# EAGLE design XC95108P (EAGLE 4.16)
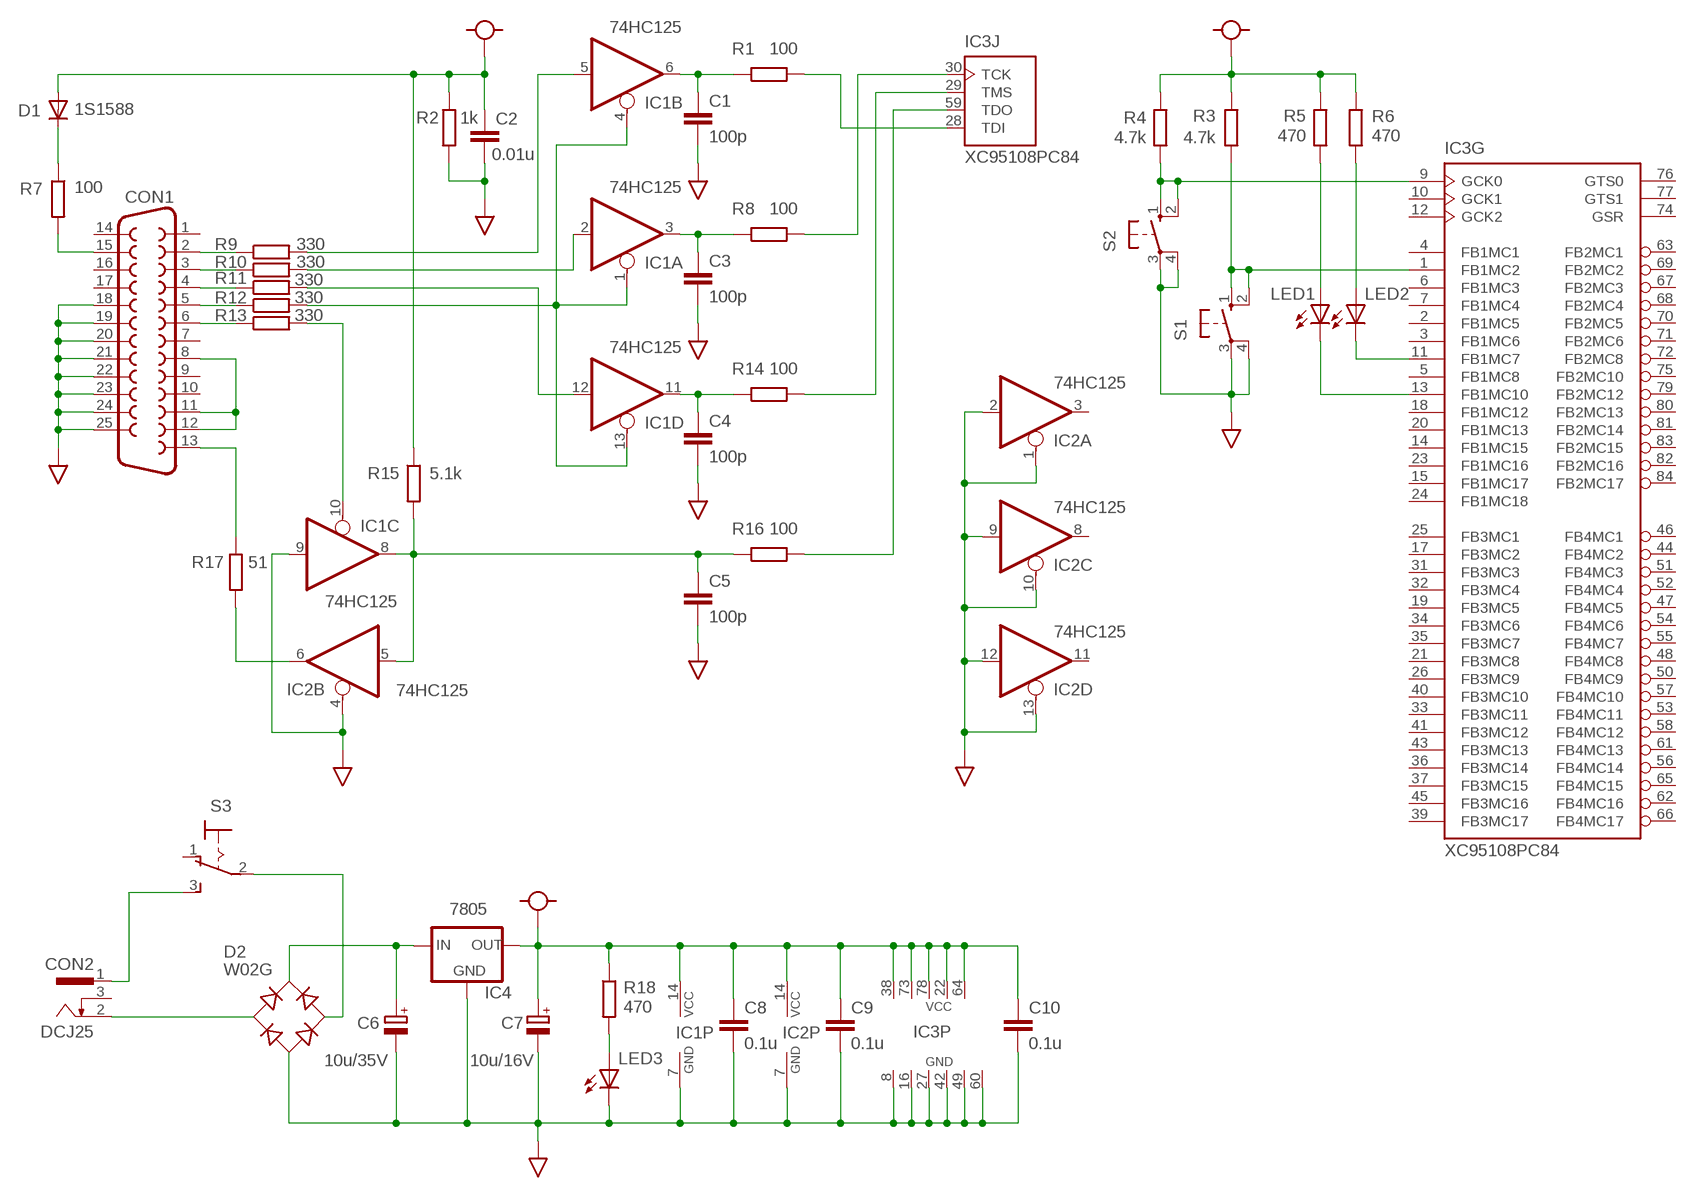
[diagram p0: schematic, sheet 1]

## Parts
C1  100p  C-CERAMIC  [C025-025X050]
C2  0.01u  C-PASS  [PASSCON]
C3  100p  C-CERAMIC  [C025-025X050]
C4  100p  C-CERAMIC  [C025-025X050]
C5  100p  C-CERAMIC  [C025-025X050]
C6  10u/35V  C-TANTALUM  [C4518]
C7  10u/16V  C-TANTALUM  [C4518]
C8  0.1u  C-PASS  [PASSCON]
C9  0.1u  C-PASS  [PASSCON]
C10  0.1u  C-PASS  [PASSCON]
CON1  DSUB25P  [F25H]
CON2  DCJ25  [SCD-014-A]
D1  1S1588  [DO41-10]
D2  W02G  [RB1A]
IC1  74HC125  74125  [DIL14]
IC2  74HC125  74125  [DIL14]
IC3  XC95108PC84  XC9572PC84  [PLCC-S84]
IC4  7805  78XXL  [78XXL]
LED1  LED3MM  [LED3MM]
LED2  LED3MM  [LED3MM]
LED3  LED3MM  [LED3MM]
R1  100  R1/8W  [0207/10]
R2  1k  R1/8W  [0207/10]
R3  4.7k  R1/8W  [0207/10]
R4  4.7k  R1/8W  [0207/10]
R5  470  R1/8W  [0207/10]
R6  470  R1/8W  [0207/10]
R7  100  R1/8W  [0207/10]
R8  100  R1/8W  [0207/10]
R9  330  R1/8W  [0207/10]
R10  330  R1/8W  [0207/10]
R11  330  R1/8W  [0207/10]
R12  330  R1/8W  [0207/10]
R13  330  R1/8W  [0207/10]
R14  100  R1/8W  [0207/10]
R15  5.1k  R1/8W  [0207/10]
R16  100  R1/8W  [0207/10]
R17  51  R1/8W  [0207/10]
R18  470  R1/8W  [0207/10]
S1  40-XX  [B3F-40XX]
S2  40-XX  [B3F-40XX]
S3  SW-TOGGLE  [SW-TOGGLE]

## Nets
GND: C1.2 C2.2 C3.2 C4.2 C5.2 C6.- C7.- C8.2 C9.2 C10.2 CON1.18 CON1.19 CON1.20 CON1.21 CON1.22 CON1.23 CON1.24 CON1.25 D2.- IC1.7(P:GND) IC1.9(C:I) IC2.1(A:OE) IC2.2(A:I) IC2.4(B:OE) IC2.7(P:GND) IC2.9(C:I) IC2.10(C:OE) IC2.12(D:I) IC2.13(D:OE) IC3.8(P:GND) IC3.16(P:GND) IC3.27(P:GND) IC3.42(P:GND) IC3.49(P:GND) IC3.60(P:GND) IC4.GND LED3.K(C) R2.2 S1.3(P) S1.4(P1) S2.3(P) S2.4(P1)
N$1: CON1.4 R11.1
N$2: IC1.5(B:I) R9.2
N$3: CON1.2 R9.1
N$4: CON1.3 R10.1
N$5: IC1.2(A:I) R10.2
N$6: CON1.15 R7.2
N$7: CON1.8 CON1.11 CON1.12
N$8: CON1.5 R12.1
N$9: CON1.6 R13.1
N$10: IC1.12(D:I) R11.2
N$11: IC1.10(C:OE) R13.2
N$12: IC3.11(G:FB1MC7) LED2.K(C)
N$13: C3.1 IC1.3(A:O) R8.1
N$14: CON1.13 R17.1
N$15: D1.C R7.1
N$16: C5.1 IC1.8(C:O) IC2.5(B:I) R15.2 R16.1
N$17: LED3.A R18.2
N$18: C1.1 IC1.6(B:O) R1.1
N$19: IC2.6(B:O) R17.2
N$20: C4.1 IC1.11(D:O) R14.1
N$21 [AC]: CON2.2 D2.AC1
N$22: IC3.13(G:FB1MC10) LED1.K(C)
N$23 [AC]: C6.+ D2.+ IC4.IN
N$26: IC1.1(A:OE) IC1.4(B:OE) IC1.13(D:OE) R12.2
N$27: IC3.30(J:TCK) R8.2
N$28: IC3.29(J:TMS) R14.2
N$29: IC3.59(J:TDO) R16.2
N$30: IC3.28(J:TDI) R1.2
N$31: IC3.9(G:GCK0) R4.2 S2.1(S) S2.2(S1)
N$32: LED1.A R5.2
N$33: LED2.A R6.2
N$34 [AC]: D2.AC2 S3.2(P)
N$35: IC3.1(G:FB1MC2) R3.2 S1.1(S) S1.2(S1)
N$37 [AC]: CON2.1 S3.3(S)
VCC [Vcc]: C2.1 C7.+ C8.1 C9.1 C10.1 D1.A IC1.14(P:VCC) IC2.14(P:VCC) IC3.22(P:VCC) IC3.38(P:VCC) IC3.64(P:VCC) IC3.73(P:VCC) IC3.78(P:VCC) IC4.OUT R2.1 R3.1 R4.1 R5.1 R6.1 R15.1 R18.1
Unconnected: CON1.1 CON1.7 CON1.9 CON1.10 CON1.14 CON1.16 CON1.17 CON2.3 IC2.3(A:O) IC2.8(C:O) IC2.11(D:O) IC3.2(G:FB1MC5) IC3.3(G:FB1MC6) IC3.4(G:FB1MC1) IC3.5(G:FB1MC8) IC3.6(G:FB1MC3) IC3.7(G:FB1MC4) IC3.10(G:GCK1) IC3.12(G:GCK2) IC3.14(G:FB1MC15) IC3.15(G:FB1MC17) IC3.17(G:FB3MC2) IC3.18(G:FB1MC12) IC3.19(G:FB3MC5) IC3.20(G:FB1MC13) IC3.21(G:FB3MC8) IC3.23(G:FB1MC16) IC3.24(G:FB1MC18) IC3.25(G:FB3MC1) IC3.26(G:FB3MC9) IC3.31(G:FB3MC3) IC3.32(G:FB3MC4) IC3.33(G:FB3MC11) IC3.34(G:FB3MC6) IC3.35(G:FB3MC7) IC3.36(G:FB3MC14) IC3.37(G:FB3MC15) IC3.39(G:FB3MC17) IC3.40(G:FB3MC10) IC3.41(G:FB3MC12) IC3.43(G:FB3MC13) IC3.44(G:FB4MC2) IC3.45(G:FB3MC16) IC3.46(G:FB4MC1) IC3.47(G:FB4MC5) IC3.48(G:FB4MC8) IC3.50(G:FB4MC9) IC3.51(G:FB4MC3) IC3.52(G:FB4MC4) IC3.53(G:FB4MC11) IC3.54(G:FB4MC6) IC3.55(G:FB4MC7) IC3.56(G:FB4MC14) IC3.57(G:FB4MC10) IC3.58(G:FB4MC12) IC3.61(G:FB4MC13) IC3.62(G:FB4MC16) IC3.63(G:FB2MC1) IC3.65(G:FB4MC15) IC3.66(G:FB4MC17) IC3.67(G:FB2MC3) IC3.68(G:FB2MC4) IC3.69(G:FB2MC2) IC3.70(G:FB2MC5) IC3.71(G:FB2MC6) IC3.72(G:FB2MC8) IC3.74(G:GSR) IC3.75(G:FB2MC10) IC3.76(G:GTS0) IC3.77(G:GTS1) IC3.79(G:FB2MC12) IC3.80(G:FB2MC13) IC3.81(G:FB2MC14) IC3.82(G:FB2MC16) IC3.83(G:FB2MC15) IC3.84(G:FB2MC17) S3.1(O)

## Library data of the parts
C1 C3-C5 = xc95108p:C-CERAMIC: Ceramic Conenser
C2 C8-C10 = xc95108p:C-PASS: Monolithic Ceramic Condenser
C6 C7 = xc95108p:C-TANTALUM: Tantalum Condenser
CON1 = xc95108p:DSUB25P: IBM PC/AT Parallel Connector
CON2 = xc95108p:DCJ25: Standerd AC Adupter Jack
D1 = xc95108p:1S1588: Small Signal Diode
D2 = xc95108p:W02G: Bridge Diode
IC1 IC2 = xc95108p:74125: Quad bus BUFFER, 3-state
IC3 = XILINX:XC9572PC84: CPLD
IC4 = xc95108p:78XXL: Voltage Regurator, Up to 1A
LED1-LED3 = xc95108p:LED3MM: LED
R1-R18 = xc95108p:R1/8W: Carbon Resistor
S1 S2 = olimex-r0land:40-XX: OMRON SWITCH
S3 = xc95108p:SW-TOGGLE: Toggle Switch

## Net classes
1 AC: width 0.762 mm
2 Vcc: width 0.508 mm

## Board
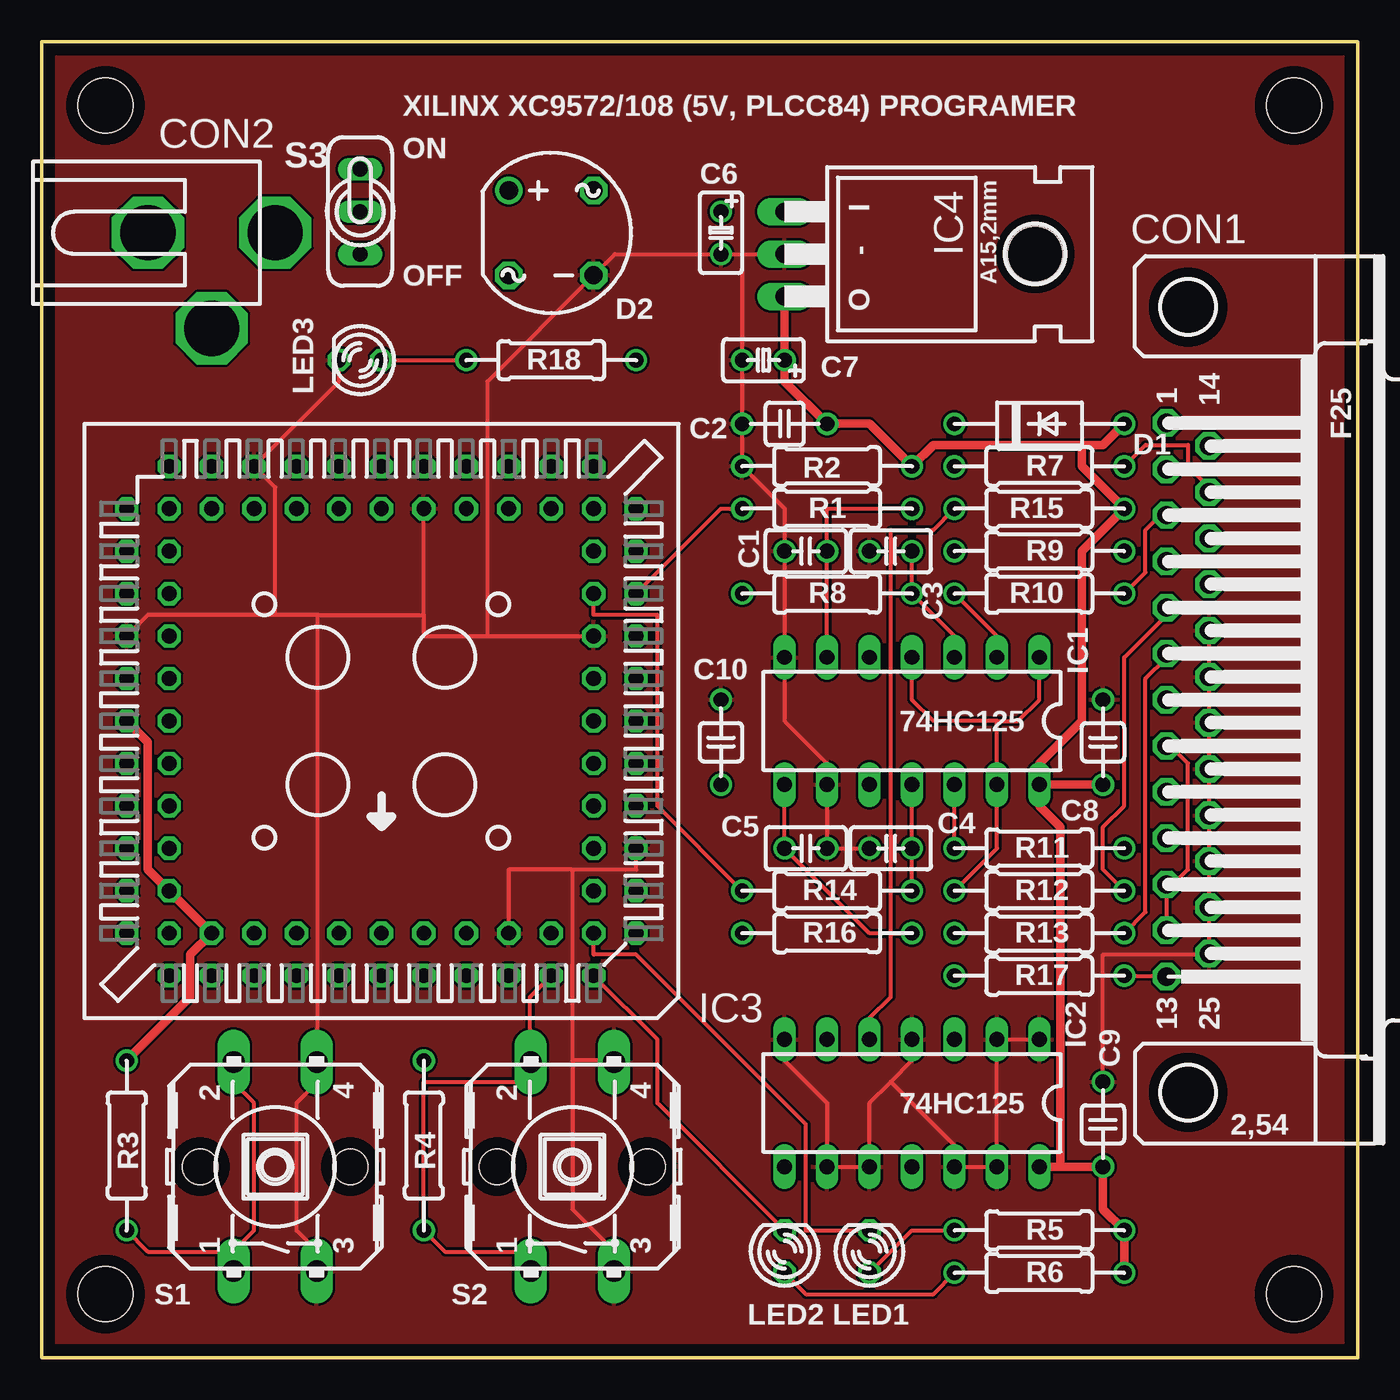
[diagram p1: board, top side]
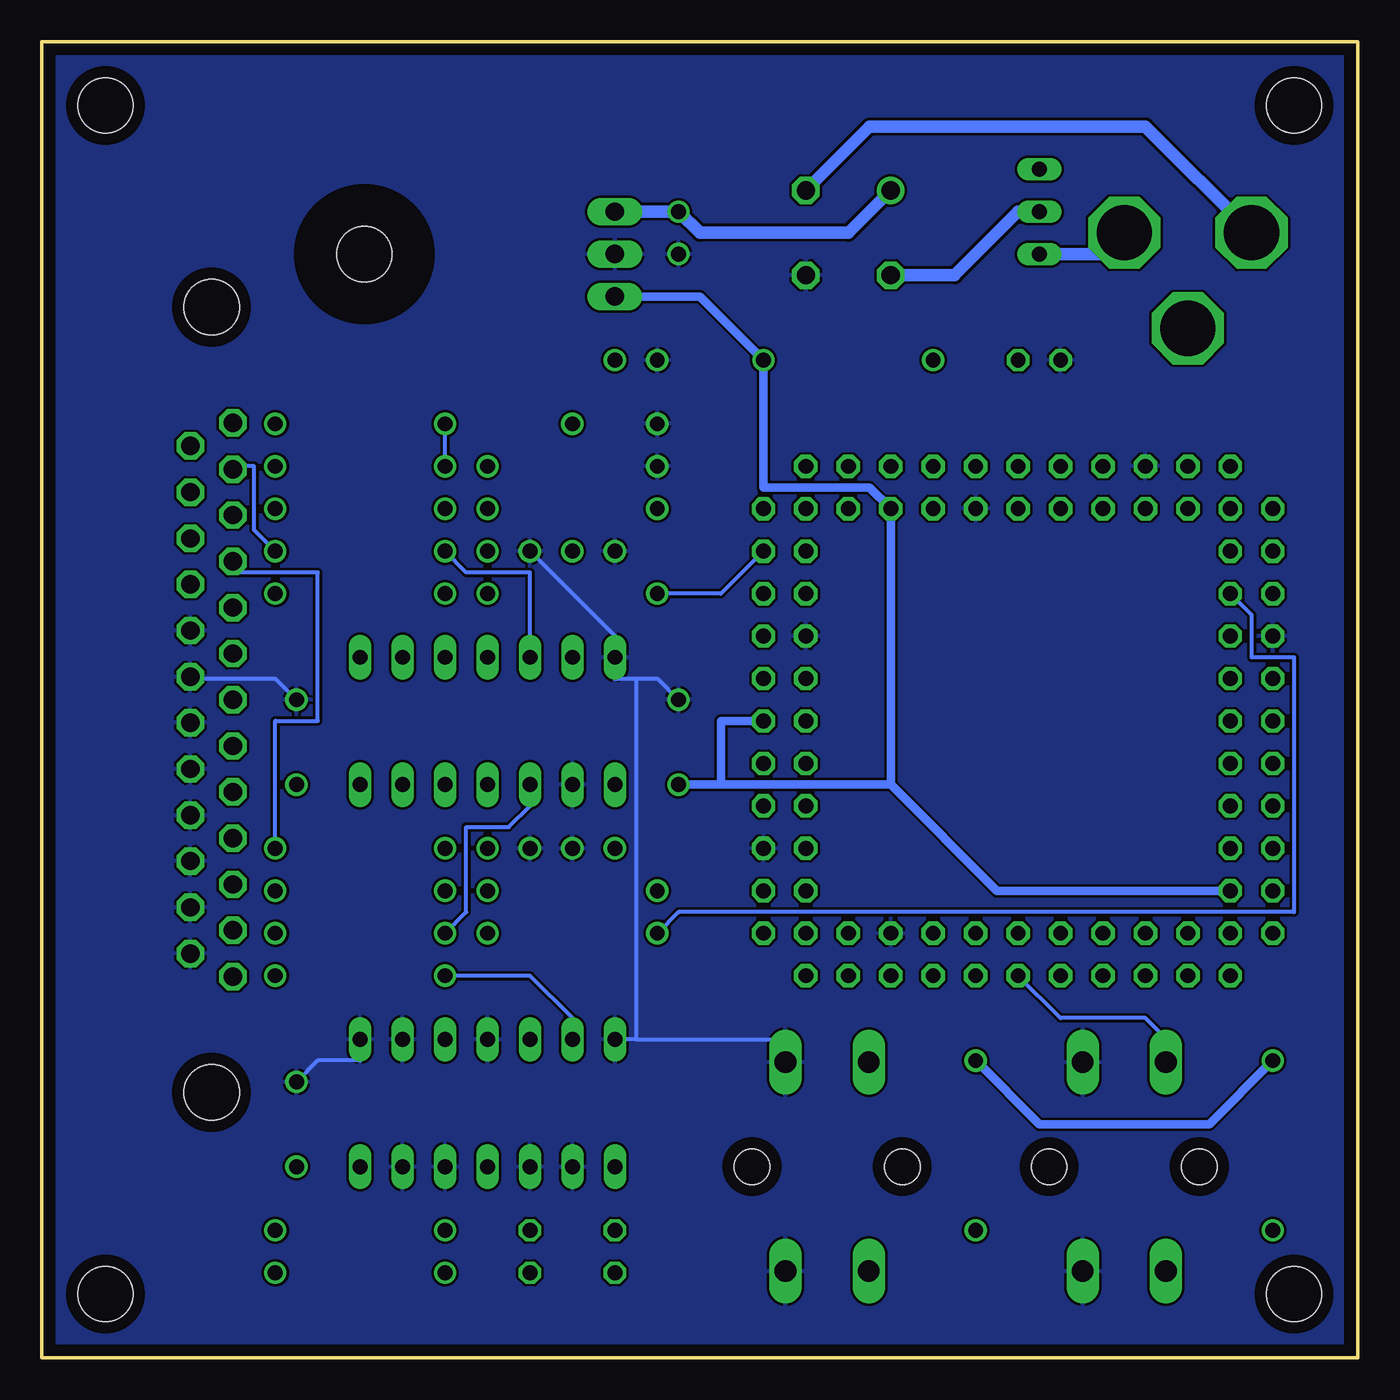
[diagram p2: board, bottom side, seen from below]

Size 78.74 x 78.74 mm. Coordinates in mm from the lower left corner, seen from the top.
Outline: 0,0 0,78.74 78.74,78.74 78.74,0 0,0
Copper layers (1*16): Top 0.035mm / dielectric 1.5mm / Bottom 0.035mm
Design rules "p-ban_min": minimum track width 0.15mm, minimum drill 0.3mm, track to track 0.15mm, track to pad 0.15mm, pad to pad 0.15mm, via to via 0.15mm, smd to smd 0.15mm, copper to edge 0.7mm, drill to drill 0.45mm, minimum pad ring 0.15mm, minimum via ring 0.15mm, stop-mask expansion 4mil, vias tented up to drill 0mil, thermal gap 0.15mm
Holes 3.3 mm at 74.93,74.93 74.93,3.81 3.81,3.81 3.81,74.93

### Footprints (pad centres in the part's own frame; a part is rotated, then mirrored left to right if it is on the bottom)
C025-025X050 = drill 0.889 round: 1 -1.27,0; 2 1.27,0
PASSCON = drill 0.889 round: 1 -1.27,0; 2 3.81,0
C4518 = drill 0.889 round: + -1.27,0; - 1.27,0
F25H = drill 1.092 octagon: 1 -16.561,-10.16; 2 -13.792,-10.16; 3 -11.049,-10.16; 4 -8.28,-10.16; 5 -5.512,-10.16; 6 -2.769,-10.16; 7 0,-10.16; 8 2.769,-10.16; 9 5.512,-10.16; 10 8.28,-10.16; 11 11.049,-10.16; 12 13.792,-10.16; 13 16.561,-10.16; 14 -15.189,-7.62; 15 -12.421,-7.62; 16 -9.652,-7.62; 17 -6.909,-7.62; 18 -4.14,-7.62; 19 -1.372,-7.62; 20 1.372,-7.62; 21 4.14,-7.62; 22 6.909,-7.62; 23 9.652,-7.62; 24 12.421,-7.62; 25 15.189,-7.62 | hole 3.302: -23.495,-8.89; 23.495,-8.89
SCD-014-A = drill 3.302 octagon: 1 0,12.065; 2 0,4.445; 3 5.715,8.255
DO41-10 = drill 0.889 round: A 5.08,0; C -5.08,0
RB1A = drill 1.092 round: + -2.54,2.54 | drill 1.092 octagon: - 2.54,-2.54; AC1 2.54,2.54; AC2 -2.54,-2.54
DIL14 = drill 0.889 long: 1 -7.62,-3.81; 2 -5.08,-3.81; 3 -2.54,-3.81; 4 0,-3.81; 5 2.54,-3.81; 6 5.08,-3.81; 7 7.62,-3.81; 8 7.62,3.81; 9 5.08,3.81; 10 2.54,3.81; 11 0,3.81; 12 -2.54,3.81; 13 -5.08,3.81; 14 -7.62,3.81
PLCC-S84 = drill 0.889 pad 1.397 octagon: 1 0,15.24; 2 0,12.7; 3 -2.54,15.24; 4 -2.54,12.7; 5 -5.08,15.24; 6 -5.08,12.7; 7 -7.62,15.24; 8 -7.62,12.7; 9 -10.16,15.24; 10 -10.16,12.7; 11 -12.7,15.24; 12 -15.24,12.7; 13 -12.7,12.7; 14 -15.24,10.16; 15 -12.7,10.16; 16 -15.24,7.62; 17 -12.7,7.62; 18 -15.24,5.08; 19 -12.7,5.08; 20 -15.24,2.54; 21 -12.7,2.54; 22 -15.24,0; 23 -12.7,0; 24 -15.24,-2.54; 25 -12.7,-2.54; 26 -15.24,-5.08; 27 -12.7,-5.08; 28 -15.24,-7.62; 29 -12.7,-7.62; 30 -15.24,-10.16; 31 -12.7,-10.16; 32 -15.24,-12.7; 33 -12.7,-15.24; 34 -12.7,-12.7; 35 -10.16,-15.24; 36 -10.16,-12.7; 37 -7.62,-15.24; 38 -7.62,-12.7; 39 -5.08,-15.24; 40 -5.08,-12.7; 41 -2.54,-15.24; 42 -2.54,-12.7; 43 0,-15.24; 44 0,-12.7; 45 2.54,-15.24; 46 2.54,-12.7; 47 5.08,-15.24; 48 5.08,-12.7; 49 7.62,-15.24; 50 7.62,-12.7; 51 10.16,-15.24; 52 10.16,-12.7; 53 12.7,-15.24; 54 15.24,-12.7; 55 12.7,-12.7; 56 15.24,-10.16; 57 12.7,-10.16; 58 15.24,-7.62; 59 12.7,-7.62; 60 15.24,-5.08; 61 12.7,-5.08; 62 15.24,-2.54; 63 12.7,-2.54; 64 15.24,0; 65 12.7,0; 66 15.24,2.54; 67 12.7,2.54; 68 15.24,5.08; 69 12.7,5.08; 70 15.24,7.62; 71 12.7,7.62; 72 15.24,10.16; 73 12.7,10.16; 74 15.24,12.7; 75 12.7,15.24; 76 12.7,12.7; 77 10.16,15.24; 78 10.16,12.7; 79 7.62,15.24; 80 7.62,12.7; 81 5.08,15.24; 82 5.08,12.7; 83 2.54,15.24; 84 2.54,12.7
78XXL = drill 1.092 long: GND 0,-3.81; IN -2.54,-3.81; OUT 2.54,-3.81 | hole 3.302: 0,11.176
LED3MM = drill 0.889 octagon: A -1.27,0; K 1.27,0
0207/10 = drill 0.889 round: 1 -5.08,0; 2 5.08,0
B3F-40XX = drill 1.295 long: 1 -6.248,2.489; 2 6.248,2.489; 3 -6.248,-2.489; 4 6.248,-2.489 | hole 2.108: 0,-4.496; 0,4.496
SW-TOGGLE = drill 0.889 long: 1 0,-2.54; 2 0,0; 3 0,2.54

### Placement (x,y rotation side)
C1  45.72,48.26 180 top
C2  45.72,55.88 180 top
C3  50.8,48.26 180 top
C4  50.8,30.48 180 top
C5  45.72,30.48 0 top
C6  40.64,67.31 270 top
C7  43.18,59.69 180 top
C8  63.5,35.56 90 top
C9  63.5,12.7 90 top
C10  40.64,35.56 90 top
CON1  77.47,39.37 270 top
CON2  1.91,67.31 270 top
D1  59.69,55.88 0 top
D2  30.48,67.31 0 top
IC1  52.07,38.1 180 top
IC2  52.07,15.24 180 top
IC3  20.32,38.1 180 top
IC4  48.26,66.04 270 top
LED1  49.53,6.35 90 top
LED2  44.45,6.35 90 top
LED3  19.05,59.69 180 top
R1  46.99,50.8 180 top
R2  46.99,53.34 180 top
R3  5.08,12.7 270 top
R4  22.86,12.7 270 top
R5  59.69,7.62 180 top
R6  59.69,5.08 180 top
R7  59.69,53.34 0 top
R8  46.99,45.72 180 top
R9  59.69,48.26 180 top
R10  59.69,45.72 180 top
R11  59.69,30.48 180 top
R12  59.69,27.94 180 top
R13  59.69,25.4 180 top
R14  46.99,27.94 180 top
R15  59.69,50.8 180 top
R16  46.99,25.4 180 top
R17  59.69,22.86 180 top
R18  30.48,59.69 180 top
S1  13.97,11.43 90 top
S2  31.75,11.43 90 top
S3  19.05,68.58 180 top

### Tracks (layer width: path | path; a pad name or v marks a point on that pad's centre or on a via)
GND
  Top 0.254: CON1.18 CON1.19 CON1.20 CON1.21 CON1.22 CON1.23 CON1.24 CON1.25 69.85,24.13 63.5,24.13 C9.2 | IC2.7 44.45,17.78 46.99,15.24 IC2.9 IC2.10 49.53,15.24 50.8,16.51 | 50.8,16.51 52.07,17.78 IC2.4 | IC2.1 IC2.2 IC2.13 IC2.12 54.61,12.7 50.8,16.51 | 31.75,29.21 27.94,29.21 IC3.8 | 31.75,29.21 35.56,29.21 IC3.16 | 31.75,17.78 31.75,29.21 | 31.75,17.78 31.75,8.89 34.29,6.35 S2.3 | 31.75,17.78 34.29,17.78 S2.4 | 41.91,66.04 C6.- 34.29,66.04 D2.- 26.67,58.42 26.67,43.18 | 41.91,66.04 IC4.GND | C4.2 C5.2 IC1.9 46.99,35.56 44.45,38.1 IC1.7 C1.2 44.45,50.8 R2.2 C2.2 C7.- 41.91,66.04 | S1.3 16.51,6.35 15.24,7.62 15.24,15.24 16.51,16.51 S1.4 16.51,19.05 16.51,44.45 | LED3.K 17.78,58.42 IC3.49 13.97,52.07 13.97,44.45 | IC3.60 6.35,44.45 13.97,44.45 | 16.51,44.45 22.86,44.45 | 16.51,44.45 13.97,44.45 | 22.86,44.45 IC3.42 | 26.67,43.18 22.86,43.18 22.86,44.45 | 26.67,43.18 IC3.27
  Bottom 0.254: C8.2 64.77,40.64 69.85,40.64 CON1.19 | C9.2 62.23,17.78 59.69,17.78 IC2.1 | 43.18,19.05 34.29,19.05 S2.4 | 43.18,19.05 IC2.7 | C10.2 41.91,40.64 43.18,40.64 | 43.18,40.64 44.45,40.64 IC1.7 44.45,43.18 C3.2 | 43.18,40.64 43.18,19.05
  pour Bottom: 0,78.74 78.74,78.74 78.74,0 0,0
  pour Top: 0,78.74 78.74,78.74 78.74,0 0,0
N$1
  Bottom 0.254: R11.1 64.77,38.1 62.23,38.1 62.23,46.99 67.31,46.99 CON1.4
N$2
  Bottom 0.254: R9.2 53.34,46.99 49.53,46.99 IC1.5
N$3
  Bottom 0.254: R9.1 66.04,49.53 66.04,53.34 67.31,53.34 CON1.2
N$4
  Top 0.254: R10.1 66.04,46.99 66.04,49.53 67.31,50.8 CON1.3
N$5
  Top 0.254: R10.2 57.15,43.18 IC1.2
N$6
  Top 0.254: R7.2 66.04,54.61 68.58,54.61 68.58,53.34 69.85,52.07 CON1.15
N$7
  Top 0.254: 67.31,27.94 CON1.12 67.31,25.4 | 67.31,27.94 68.58,29.21 68.58,35.56 67.31,36.83 CON1.8 | 67.31,27.94 CON1.11
N$8
  Top 0.254: R12.1 63.5,29.21 63.5,31.75 64.77,33.02 64.77,41.91 67.31,44.45 CON1.5
N$9
  Top 0.254: R13.1 66.04,26.67 66.04,40.64 67.31,41.91 CON1.6
N$10
  Top 0.254: R11.2 IC1.12
N$11
  Bottom 0.254: R13.2 53.34,26.67 53.34,31.75 50.8,31.75 49.53,33.02 IC1.10
N$12
  Top 0.254: LED2.K 36.83,15.24 36.83,19.05 IC3.11
N$13
  Top 0.254: C3.1 R8.1 54.61,43.18 IC1.3
N$14
  Top 0.254: R17.1 67.31,22.86 CON1.13
N$15
  Bottom 0.254: R7.1 D1.C
N$16
  Top 0.254: IC1.8 C5.1 49.53,25.4 50.8,25.4 | 50.8,25.4 R16.1 | IC2.5 49.53,20.32 50.8,21.59 50.8,25.4 | R15.2 53.34,49.53 50.8,49.53 50.8,25.4
N$17
  Top 0.254: LED3.A R18.2
N$18
  Top 0.254: IC1.6 C1.1 46.99,50.8 R1.1
N$19
  Bottom 0.254: R17.2 49.53,22.86 46.99,20.32 IC2.6
N$20
  Top 0.254: R14.1 C4.1 IC1.11
N$21
  Bottom 0.762: D2.AC1 29.21,73.66 12.7,73.66 CON2.2
N$22
  Top 0.254: LED1.K 45.72,7.62 45.72,13.97 35.56,24.13 33.02,24.13 IC3.13
N$23
  Bottom 0.762: IC4.IN C6.+ 39.37,67.31 30.48,67.31 D2.+
N$26
  Top 0.254: R12.2 57.15,30.48 IC1.13 57.15,38.1 | 57.15,38.1 53.34,38.1 52.07,39.37 IC1.4 | 57.15,38.1 58.42,38.1 59.69,39.37 IC1.1
N$27
  Bottom 0.254: IC3.30 38.1,45.72 R8.2
N$28
  Top 0.254: R14.2 36.83,33.02 36.83,44.45 33.02,44.45 IC3.29
N$29
  Bottom 0.254: IC3.59 6.35,44.45 6.35,41.91 3.81,41.91 3.81,26.67 40.64,26.67 R16.2
N$30
  Top 0.254: IC3.28 40.64,50.8 R1.2
N$31
  Top 0.254: IC3.9 29.21,21.59 29.21,19.05 S2.2 29.21,16.51 22.86,16.51 R4.2 24.13,6.35 29.21,6.35 S2.1
N$32
  Top 0.254: LED1.A 52.07,7.62 R5.2
N$33
  Top 0.254: LED2.A 45.72,3.81 53.34,3.81 R6.2
N$34
  Bottom 0.762: D2.AC2 24.13,64.77 20.32,68.58 S3.2
N$35
  Top 0.254: R3.2 6.35,6.35 11.43,6.35 | 11.43,6.35 12.7,7.62 12.7,15.24 11.43,16.51 S1.2 | 11.43,6.35 S1.1
  Bottom 0.254: S1.1 11.43,6.35 | IC3.1 17.78,20.32 12.7,20.32 11.43,19.05 S1.2
N$37
  Bottom 0.762: S3.3 15.24,66.04 CON2.1
VCC
  Top 0.508: R3.1 8.89,21.59 8.89,24.13 IC3.78 | IC3.78 IC3.73 | IC3.64 6.35,36.83 6.35,29.21 IC3.73 | IC3.78 IC3.73 | IC1.14 C8.1 | R6.1 R5.1 63.5,8.89 C9.1 60.96,11.43 | 60.96,11.43 IC2.14 | 60.96,11.43 60.96,31.75 59.69,33.02 IC1.14 | IC4.OUT C7.+ 44.45,58.42 C2.1 49.53,55.88 R2.1 53.34,54.61 62.23,54.61 | 62.23,54.61 62.23,53.34 R15.1 62.23,48.26 62.23,38.1 59.69,35.56 IC1.14 | 62.23,54.61 63.5,54.61 D1.A
  Bottom 0.508: 27.94,34.29 IC3.38 29.21,52.07 35.56,52.07 R18.1 39.37,63.5 IC4.OUT | 39.37,34.29 C10.1 | 27.94,34.29 39.37,34.29 | 39.37,34.29 38.1,34.29 38.1,38.1 IC3.22 | R4.1 19.05,13.97 8.89,13.97 R3.1 | 27.94,34.29 21.59,27.94 IC3.73

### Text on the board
tPlace: XILINX XC9572/108 (5V, PLCC84) PROGRAMER | ON | OFF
